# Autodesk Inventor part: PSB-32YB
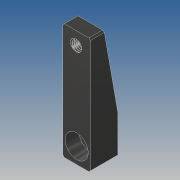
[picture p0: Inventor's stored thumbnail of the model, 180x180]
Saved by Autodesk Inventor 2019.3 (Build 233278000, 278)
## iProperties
Created: 2010-02
Part Number: PSB-32YB
Material: Ogólny
Document SubType Name: Modeling
Designer: CADENGINEERING4
Density: 1 g/cm^3
Appearance: Ciemnoszara
Author: CADENGINEERING4
Revision Number: 1LAST_VERSION
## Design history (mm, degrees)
feature "Baza1"
node "Bryła1"
